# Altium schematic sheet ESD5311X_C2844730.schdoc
size 127 x 101 mm
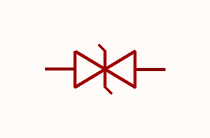
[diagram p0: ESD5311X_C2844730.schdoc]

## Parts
U?  esd5311x_c2844730  [DFN1006-2L-BI]  (value not drawn)

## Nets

Not connected (* = marked no-connect by the designer): U? 1 2

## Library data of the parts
U? = esd5311x_c2844730: 极性:双向;反向截止电压(Vrwm):5V;最大钳位电压:21V;峰值脉冲电流(Ipp):4A;峰值脉冲功率(Ppp):80W;击穿电压:7.5V;; Manufacturer: TECH PUBLIC(台舟); AddInBom: yes; ModelId: 2bdbcca3b35b49c5a8ae725a08658930; ModelTransform: 40.1574,24.4094,0,0,0,0,0,0,0; polarity: 双向; Reverse Stand-Off Voltage (Vrwm): 5V; Maximum Clamping Voltage: 21V; Peak Pulse Current (Ipp): 4A; Peak Pulse Power Dissipation (Ppp): 80W; Breakdown Voltage: 7.5V; Reverse Leakage Current (Ir): 80nA; Number of Lines: 单路; level of protection: IEC 61000-4-2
